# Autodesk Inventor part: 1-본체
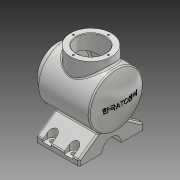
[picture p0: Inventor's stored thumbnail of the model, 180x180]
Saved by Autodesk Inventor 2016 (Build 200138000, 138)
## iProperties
Created: 2017-04
Part Number: 1-본체
Material: 알루미늄 6061
Document SubType Name: Modeling
Designer: H
Density: 2.7 g/cm^3
Appearance: 알루미늄 - 평지
Mass: 1664.76 g
Surface Area: 1067.86 cm^2
Volume: 616.577 cm^3
Author: H
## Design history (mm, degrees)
sketch "스케치2"
  geometry: L1 (48.168, 132)-(-48.168, 132); L2 (-59.832, 82)-(48.168, 82); L3 (48.168, 82)-(48.168, 132); A1 r 113 centre (53.168, 82) between (-48.168, 132) and (-59.832, 82); 3 further points
  constraints: 6 end point, 2 midpoint, 2 point on circle, 1 centre point, 1 horizontal, 1 parallel, 1 point on line, 1 vertical
  dimensions: "d2" = 108 distance from line of L2.start L3; "d3" = 82 vertical distance of L2.start point (0, 0); "d4" = 100 diameter of L1 L2; "d5" = 113 radius of A1; "d96" = 0 horizontal distance of point (0, 0) point (0, 132)
revolve "회전1" sketch "스케치2" stored, may be unused: angle "d6" = 90 deg
node "작업 평면1"
sketch "스케치4"
  geometry: L1 (-48.168, 50)-(-48.168, -50) reference; C1 r 38 at (1.832, 0); 1 further point
  constraints: 1 centre point, 1 horizontal alignment
  dimensions: "d74" = 50 distance from line of L1 C1.centre; "d75" = 76 diameter of C1
extrude "돌출1" join sketch "스케치4" stored distance "d9" = 10; taper "d10" = 0 deg
sketch "스케치5"
  geometry: C1 r 38 at (0, 0); C2 r 50 at (0, 0) reference; 1 further point
  constraints: 1 centre point, 1 concentric
  dimensions: "d11" = 76 diameter of C1
extrude "돌출2" join sketch "스케치5" distance "d12" = 12; taper "d13" = 0 deg
feature "쉘1" dims "d14" = 10, "d15" = 11
sketch "스케치6"
  geometry: L1 (60, 10)-(-60, 10); L2 (-60, 10)-(-60, 0); L3 (-60, 0)-(60, 0); L4 (60, 0)-(60, 10); L5 (60, 10)-(14.299, 42); L6 (14.299, 42)-(-14.299, 42); L7 (-14.299, 42)-(-60, 10); 4 further points
  constraints: 14 end point, 2 horizontal, 2 midpoint, 2 parallel, 1 coincident, 1 equal length, 1 perpendicular, 1 vertical alignment, 1 other
  dimensions: "d16" = 120 distance of L2.end L3.end; "d17" = 10 distance of L1.end L2.end; "d18" = 55 deg angle of L4 L5
extrude "돌출3" join sketch "스케치6" stored distance "d19" = 80; taper "d20" = 0 deg
sketch "스케치7"
  geometry: C1 r 18 at (0, 0); 1 further point
  constraints: 1 centre point, 1 coincident
  dimensions: "d21" = 18 radius of C1
extrude "돌출4" cut sketch "스케치7" stored distance "d22" = 80; taper "d23" = 0 deg
node "작업 평면2"
sketch "스케치10"
  geometry: L1 (20, -50)-(20, -70); L2 (12, -50)-(12, -70); L3 (28, -70)-(28, -50); L4 (-40, -60)-(40, -60) reference; L5 (40, -21.584)-(40, -60) reference; A1 r 8 centre (20, -50) between (28, -50) and (12, -50); A2 r 8 centre (20, -70) between (12, -70) and (28, -70); 2 further points
  constraints: 8 end point, 4 point on circle, 4 tangent, 2 centre point, 1 midpoint, 1 parallel, 1 point on line, 1 vertical
  dimensions: "d27" = 20 distance between parallel lines of L5 L1; "d28" = 10 distance from line of L4 L1.start; "d29" = 16 distance between parallel lines of L2 L3
extrude "돌출5" cut sketch "스케치10" distance "d30" = 24; taper "d31" = 0 deg
hole "구멍1" diameter "d34" = 8; stored, may be unused: countersink angle "d38" = 90 deg, drill point angle "d40" = 118 deg; dims "d32" = 10, "d33" = 10, "d35" = 6, "d36" = 4, "d37" = 2, "d39" = 8
sketch "스케치11"
  geometry: L1 (0, 0)-(32.5, 0); C1 r 38 at (0, 0) reference; 2 further points
  constraints: 2 coincident, 2 end point, 1 horizontal
  dimensions: "d41" = 32.5 distance of L1.start L1.end
hole "구멍2" sketch "스케치11" at (32.5, 0) diameter "d42" = 3.242; stored, may be unused: countersink angle "d46" = 90 deg, drill point angle "d48" = 118 deg; dims "d43" = 8, "d44" = 4, "d45" = 2, "d47" = 10
sketch "스케치14"
  geometry: L1 (0, 0)-(32.5, 0); C1 r 38 at (0, 0) reference; 2 further points
  constraints: 2 coincident, 2 end point, 1 horizontal
  dimensions: "d84" = 32.5 distance of L1.start L1.end
hole "구멍5" sketch "스케치14" at (32.5, 0) diameter "d85" = 3.242; stored, may be unused: countersink angle "d89" = 90 deg, drill point angle "d91" = 118 deg; dims "d86" = 8, "d87" = 4, "d88" = 2, "d90" = 10
node "작업 평면3"
chamfer "모따기1" distance "d66" = 1; stored, may be unused: second distance "d67" = 2, angle "d68" = 45 deg
fillet "모깎기1" dims "d69" = 3
fillet "모깎기2" dims "d70" = 3
fillet "모깎기3" dims "d71" = 3
fillet "모깎기4" dims "d72" = 3
sketch "스케치13"
  geometry: L1 (18, -82)-(60, -82) reference; 2 further points
  constraints: 1 vertical alignment, 1 other
  dimensions: "d63" = 82 distance from line of L1 point (0, 0)
feature "엠보싱1" sketch "스케치13" dims "d2" = 108, "d3" = 82, "d4" = 100, "d5" = 113, "d64" = 0.5, "d65" = 0, "d96" = 0
fillet "모깎기5" dims "d73" = 3
fillet "모깎기6" dims "d95" = 3
node "솔리드1"
mirror "대칭3"
mirror "대칭4"
pattern_circular "원형 패턴1" dims angle "d50" = 360 deg
pattern_circular "원형 패턴3" dims angle "d93" = 360 deg
other parameters: "d7" = 147
